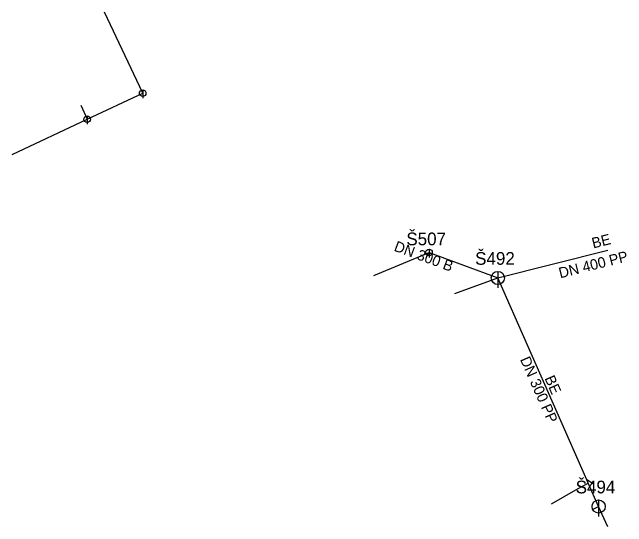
# Model space of a CAD drawing. Extents: x -505019.2 to -504926, y -1117666.2 to -1117588.3.
import ezdxf

# ---------------------------------------------------------------- set-up
doc = ezdxf.new("R2010")
doc.units = 0
for name, color, linetype in [('_pripojka_kanal_destova_prevzato_z_dokumentace_', 7, 'Continuous'), ('_pripojka_kanal_jednotna_prevzato_z_dokumentace_', 7, 'Continuous'), ('_pripojka_kanal_jednotna_priblizne_', 7, 'Continuous'), ('_sachta_kanal_', 7, 'Continuous'), ('_stoka_jednotna_smvak_prevzato_z_dokumentace_', 7, 'Continuous'), ('Default', 7, 'Continuous'), ('MoLevel 119', 7, 'Continuous'), ('MoLevel 120', 7, 'Continuous'), ('MoLevel 126', 7, 'Continuous'), ('MoLevel 57', 7, 'Continuous'), ('MoLevel 68', 7, 'Continuous'), ('MoLevel 69', 7, 'Continuous')]:
    doc.layers.add(name, color=color, linetype=linetype)

# ---------------------------------------------------------------- blocks, each defined once
blk = doc.blocks.new('_sachta_kanal_prip_')
at = {"layer": 'Default'}
blk.add_line((0, 0.00005), (0, -0.000075), dxfattribs=at)
blk.add_circle((0, 0), 0.00005, dxfattribs=at)
blk = doc.blocks.new('_sachta_kanal_prevzato_z_dokumentace_')
at = {"layer": 'Default'}
blk.add_line((0, 0.00005), (0, -0.000075), dxfattribs=at)
blk.add_circle((0, 0), 0.00005, dxfattribs=at)

msp = doc.modelspace()

# ---------------------------------------------------------------- linework, layer by layer
at = {"layer": '_pripojka_kanal_destova_prevzato_z_dokumentace_'}
for p, q in [((-504952.12, -1117630.89), (-504945.58, -1117628.56)), ((-504931.14, -1117659.75), (-504932.07, -1117659.17))]:
    msp.add_line(p, q, dxfattribs=at)
msp.add_lwpolyline([(-504937.44, -1117662.77), (-504933.37, -1117660.48), (-504931.87, -1117659.63)], dxfattribs=at)
at = {"layer": '_pripojka_kanal_jednotna_prevzato_z_dokumentace_'}
msp.add_line((-504931.2, -1117663.62), (-504930.29, -1117663.2), dxfattribs=at)
msp.add_lwpolyline([(-504964.381, -1117628.166), (-504956.01, -1117624.7), (-504945.58, -1117628.56)], dxfattribs=at)
at = {"layer": '_pripojka_kanal_jednotna_priblizne_'}
for p, q in [((-504999.434, -1117600.571), (-505005.224, -1117588.299)), ((-505007.856, -1117604.512), (-504999.434, -1117600.571)), ((-505008.826, -1117602.39), (-505007.856, -1117604.512)), ((-505019.208, -1117609.824), (-505007.856, -1117604.512))]:
    msp.add_line(p, q, dxfattribs=at)
at = {"layer": '_stoka_jednotna_smvak_prevzato_z_dokumentace_'}
for p, q in [((-504945.58, -1117628.56), (-504928.893, -1117624.342)), ((-504928.893, -1117666.249), (-504930.29, -1117663.2))]:
    msp.add_line(p, q, dxfattribs=at)
msp.add_lwpolyline([(-504930.29, -1117663.2), (-504931.87, -1117659.63), (-504932.07, -1117659.17), (-504945.58, -1117628.56)], dxfattribs=at)

# ---------------------------------------------------------------- block references
at = {"layer": 'MoLevel 119', "xscale": 20000, "yscale": 20000}
for p in [(-504945.58, -1117628.56), (-504930.29, -1117663.2)]:
    msp.add_blockref('_sachta_kanal_prevzato_z_dokumentace_', p, dxfattribs=at)
at = {"layer": 'MoLevel 57', "xscale": 10000, "yscale": 10000}
for p in [(-504999.434, -1117600.571), (-505007.856, -1117604.512), (-504956.01, -1117624.7)]:
    msp.add_blockref('_sachta_kanal_prip_', p, dxfattribs=at)

# ---------------------------------------------------------------- texts
at = {"layer": '_sachta_kanal_'}
msp.add_text('Š507', height=1.9259, dxfattribs=at).set_placement((-504959.449, -1117623.6))
at = {"layer": 'MoLevel 120'}
for s, p in [('Š492', (-504949.019, -1117626.56)), ('Š494', (-504933.775, -1117661.2))]:
    msp.add_text(s, height=1.9259, dxfattribs=at).set_placement(p)
at = {"layer": 'MoLevel 126'}
msp.add_text('DN 300 B', height=1.6049, rotation=339.69118, dxfattribs=at).set_placement((-504961.442, -1117624.401))
at = {"layer": 'MoLevel 68'}
for s, rotation, p in [('DN 400 PP', 14.18649, (-504936.113, -1117628.622)), ('DN 300 PP', 293.8147, (-504942.243, -1117640.896))]:
    msp.add_text(s, height=1.6049, rotation=rotation, dxfattribs=at).set_placement(p)
at = {"layer": 'MoLevel 69'}
for rotation, p in [(14.18649, (-504931.097, -1117624.099)), (293.8147, (-504938.522, -1117643.752))]:
    msp.add_text('BE', height=1.6049, rotation=rotation, dxfattribs=at).set_placement(p)

doc.saveas('drawing.dxf')
